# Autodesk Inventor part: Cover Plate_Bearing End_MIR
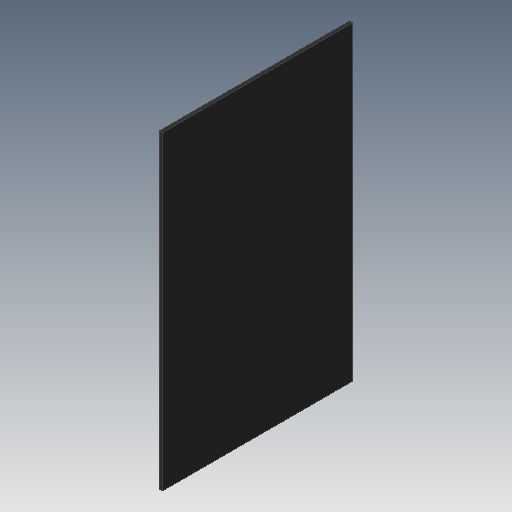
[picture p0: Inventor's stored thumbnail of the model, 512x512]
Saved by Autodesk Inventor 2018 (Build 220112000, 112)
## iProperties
Created: 2018-02
Part Number: Cover Plate_Bearing End_MIR
Material: Steel, Mild
Document SubType Name: Modeling
Designer: STK
Density: 7.85 g/cm^3
Appearance: Semi-Polished
Author: STK
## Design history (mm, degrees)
derived "Cover Plate_Bearing End.ipt"
  sketch "Sketch1"
    geometry: L1 (320.675, 196.85)-(-320.675, 196.85) reference; L2 (-320.675, 196.85)-(-320.675, -196.85) reference; L3 (-320.675, -196.85)-(320.675, -196.85) reference; L4 (320.675, -196.85)-(320.675, 196.85) reference; L5 (320.675, 196.85)-(-320.675, -196.85) reference; L6 (-320.675, 196.85)-(320.675, -196.85) reference; 1 further point
    dimensions: "d0" = 10 dimension on point (0, 0) L1.start L2.end L1.end L3.end L1 L2 L3 L4 L5 L6
feature "Solid1::Cover Plate_Bearing End.ipt" dims "d0" = 10
tag "TaggingFeature1"
body "Solid1"
